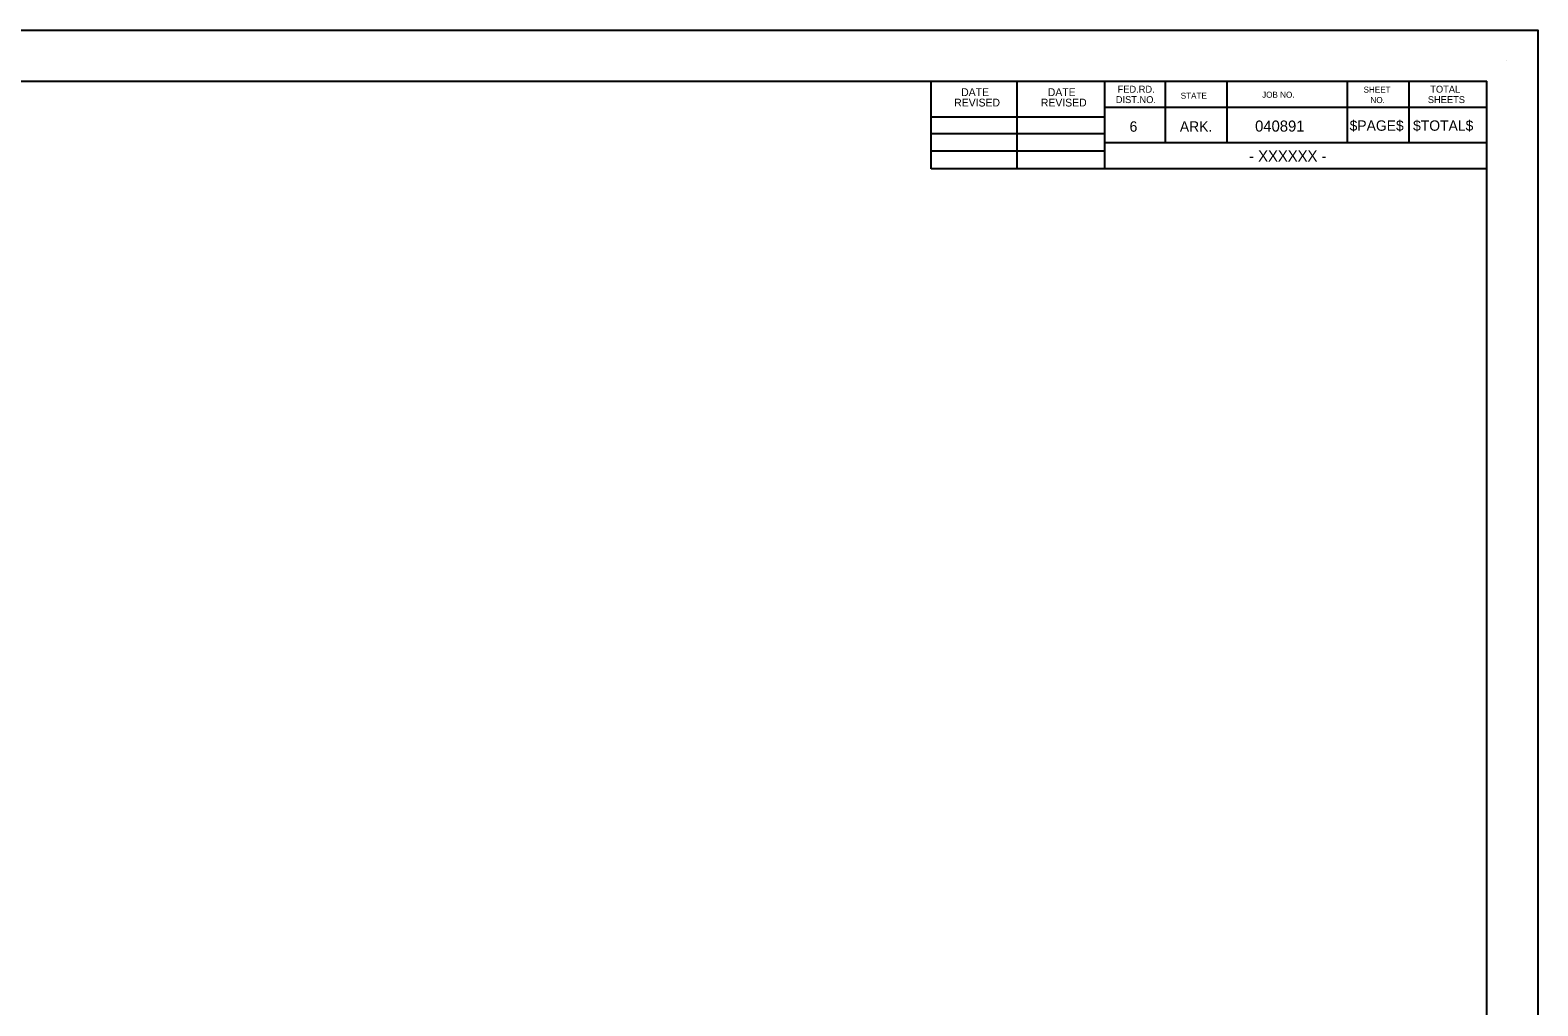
# Model space of a CAD drawing. Extents: x 16 to 1228740, y 11 to 152440.
# Drawn here: x 17.074 to 18.49, y 11.626 to 12.543 of the extents above; entities that cross this region are included whole.
import ezdxf

# ---------------------------------------------------------------- set-up
doc = ezdxf.new("R2010")
doc.units = 0
for name, color, linetype in [('B_Copy In', 7, 'Continuous'), ('B_Text', 7, 'Continuous'), ('R_Border', 7, 'Continuous'), ('R_No Plot', 7, 'Continuous')]:
    doc.layers.add(name, color=color, linetype=linetype)

msp = doc.modelspace()

# ---------------------------------------------------------------- linework, layer by layer
at = {"layer": 'R_Border'}
for p, q in [((18.4604, 12.514), (18.4604, 12.514)), ((15.7833, 12.4948), (18.4422, 12.4948)), ((17.9202, 12.4124), (17.9202, 12.4948)), ((18.0009, 12.4124), (18.0009, 12.4948)), ((18.083, 12.4948), (18.083, 12.4124)), ((18.14, 12.4948), (18.14, 12.4369)), ((18.1979, 12.4948), (18.1979, 12.4369)), ((18.311, 12.4948), (18.311, 12.4369)), ((18.3689, 12.4948), (18.3689, 12.4369)), ((18.4422, 10.7576), (18.4422, 12.4948)), ((18.4422, 12.4703), (18.083, 12.4703)), ((18.4422, 12.4704), (18.4422, 12.4704)), ((17.9202, 12.4613), (18.083, 12.4613)), ((17.9202, 12.4458), (18.083, 12.4458)), ((17.9202, 12.4296), (18.083, 12.4296)), ((18.4422, 12.4369), (18.083, 12.4369)), ((18.4422, 12.4124), (17.9202, 12.4124))]:
    msp.add_line(p, q, dxfattribs=at)
at = {"layer": 'R_No Plot'}
msp.add_lwpolyline([(15.6569, 12.5428), (18.4903, 12.5428), (18.4903, 10.7095), (15.6569, 10.7095)], close=True, dxfattribs=at)

# ---------------------------------------------------------------- texts
at = {"layer": 'B_Copy In'}
msp.add_text('      - XXXXXX -      ', height=0.0104, dxfattribs=at).set_placement((18.1958, 12.4194))
at = {"layer": 'B_Text'}
msp.add_text('040891', height=0.0104, dxfattribs=at).set_placement((18.2246, 12.4475))
at = {"layer": 'R_Border'}
for s, height, p in [('DATE', 0.00733, (17.9484, 12.4809)), ('DATE', 0.00733, (18.0298, 12.4809)), ('DIST.NO.', 0.00652, (18.0937, 12.4743)), ('FED.RD.', 0.00652, (18.0954, 12.4841)), ('STATE', 0.0057, (18.1547, 12.4784)), ('JOB NO.', 0.0057, (18.2312, 12.4793)), ('SHEET', 0.0057, (18.3265, 12.4841)), ('SHEETS', 0.00652, (18.3869, 12.4743)), ('TOTAL', 0.00652, (18.3892, 12.4841)), ('REVISED', 0.00733, (17.9419, 12.4711)), ('REVISED', 0.00733, (18.0233, 12.4711)), ('NO.', 0.0057, (18.333, 12.4743)), ('6', 0.00977, (18.1067, 12.4474)), ('ARK.', 0.00977, (18.1539, 12.4474)), ('$PAGE$', 0.00977, (18.3134, 12.4483)), ('$TOTAL$', 0.00977, (18.373, 12.4483))]:
    msp.add_text(s, height=height, dxfattribs=at).set_placement(p)

doc.saveas('drawing.dxf')
